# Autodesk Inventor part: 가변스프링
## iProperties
Created: 2015-01
Part Number: 가변스프링
Document SubType Name: Modeling
Designer: elite
Density: 7.87 g/cm^3
Material: 탄소강
Mass: 79.8318 g
Surface Area: 103.431 cm^2
Volume: 10.1438 cm^3
Author: elite
